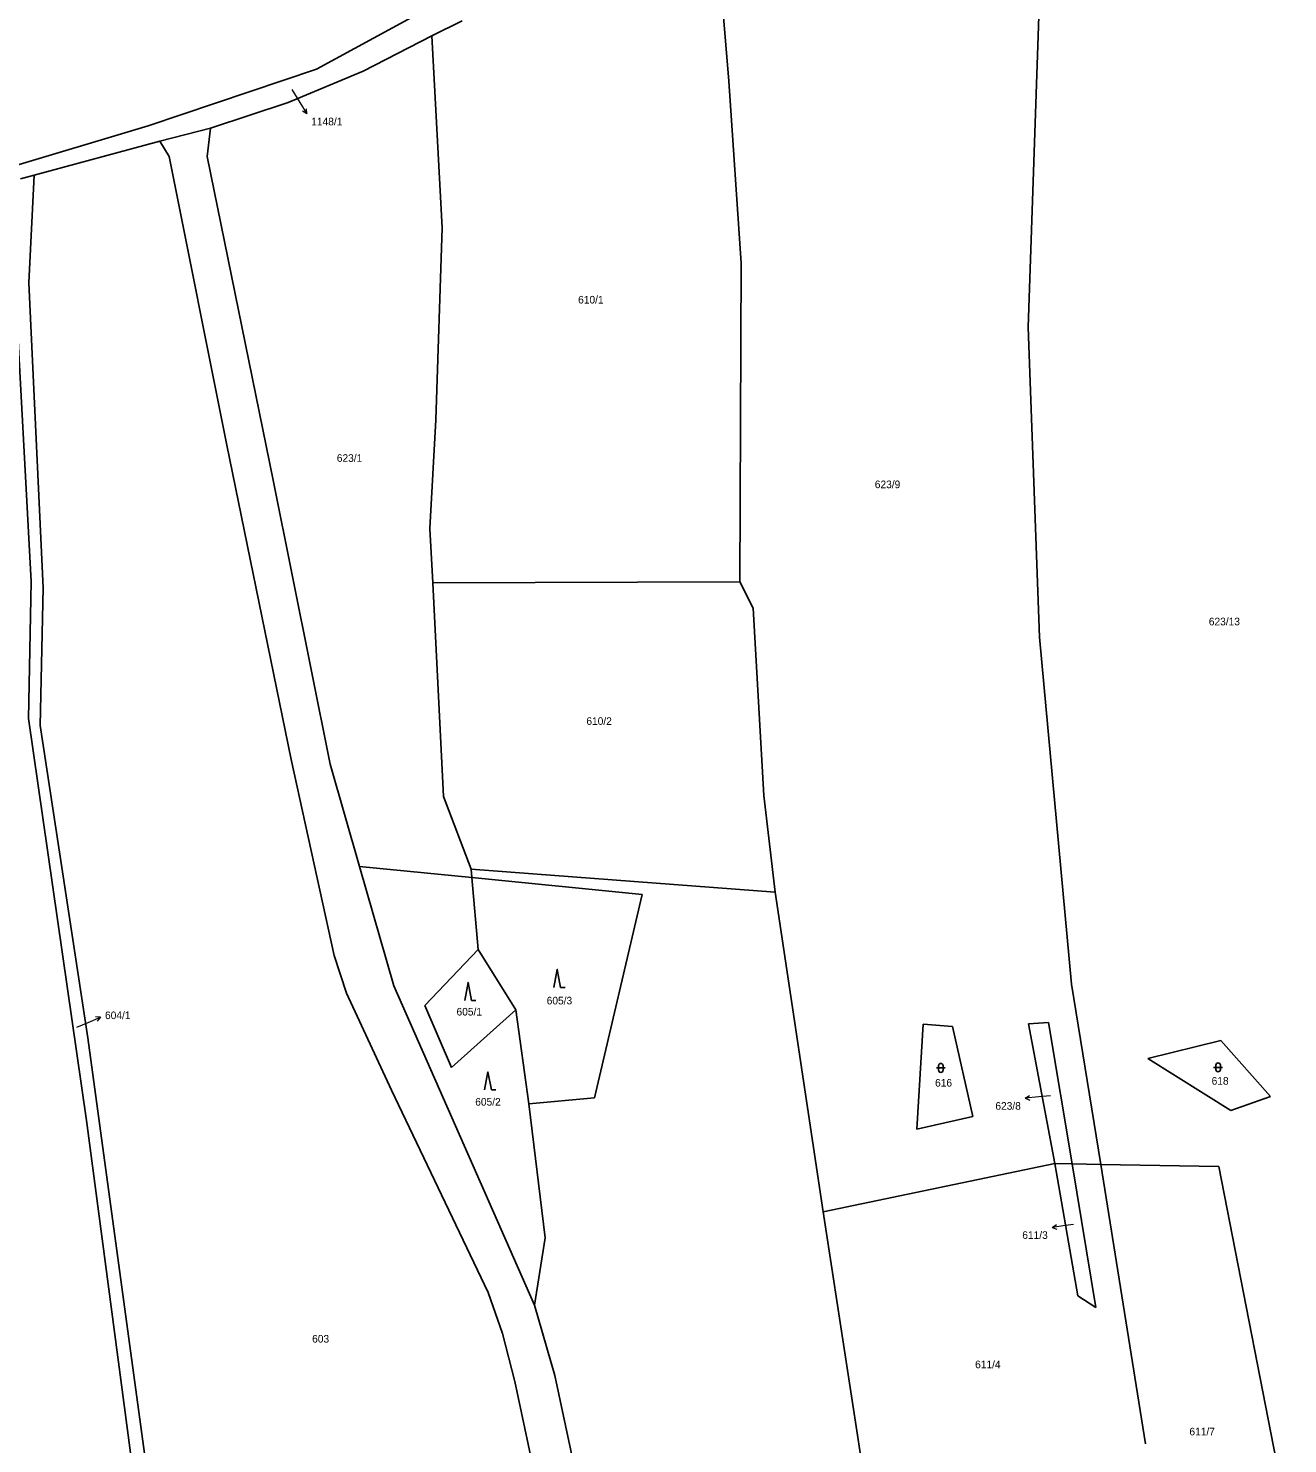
# Model space of a CAD drawing. Extents: x -765428 to -762163, y -1107632 to -1104975.
# Drawn here: x -764695.4 to -764414.2, y -1105485.1 to -1105169.2 of the extents above; entities that cross this region are included whole.
import ezdxf
from ezdxf.enums import TextEntityAlignment as Align

# ---------------------------------------------------------------- set-up
doc = ezdxf.new("R2010")
doc.units = 0
doc.header["$LTSCALE"] = 0.68
for name, color, linetype, lineweight in [('1', 7, 'Continuous', 25), ('3', 7, 'Continuous', 25), ('7', 7, 'Continuous', 13)]:
    doc.layers.add(name, color=color, linetype=linetype, lineweight=lineweight)
doc.layers.add('2', color=7, linetype='Continuous')

msp = doc.modelspace()

# ---------------------------------------------------------------- linework, layer by layer
at = {"layer": '1'}
for p, q in [((-764472.15, -1105235.89), (-764466.74, -1105081.66)), ((-764541.95, -1105146.03), (-764538.95, -1105180.96)), ((-764631.08, -1105178.3), (-764585.1, -1105153.29)), ((-764605.34, -1105170.88), (-764598.53, -1105167.48)), ((-764620.63, -1105178.73), (-764605.34, -1105170.88)), ((-764603.03, -1105213.7), (-764605.34, -1105170.88)), ((-764668.63, -1105190.94), (-764631.08, -1105178.3)), ((-764637.4, -1105185.76), (-764620.63, -1105178.73)), ((-764538.95, -1105180.96), (-764536.21, -1105221.63)), ((-764654.71, -1105191.48), (-764637.4, -1105185.76)), ((-764701.19, -1105200.73), (-764668.63, -1105190.94)), ((-764666.03, -1105194.38), (-764654.71, -1105191.48)), ((-764654.71, -1105191.48), (-764655.45, -1105197.76)), ((-764694.13, -1105201.96), (-764666.03, -1105194.38)), ((-764663.96, -1105197.76), (-764666.03, -1105194.38)), ((-764651.12, -1105262.24), (-764663.96, -1105197.76)), ((-764655.45, -1105197.76), (-764640.74, -1105270.08)), ((-764697.21, -1105202.78), (-764694.13, -1105201.96)), ((-764694.13, -1105201.96), (-764695.3, -1105225.99)), ((-764604.4, -1105256.59), (-764603.03, -1105213.7)), ((-764536.21, -1105221.63), (-764536.52, -1105292.75)), ((-764694.8, -1105292.7), (-764698.46, -1105225.08)), ((-764695.3, -1105225.99), (-764692.1, -1105294.06)), ((-764469.58, -1105305.06), (-764472.15, -1105235.89)), ((-764636.7, -1105332.4), (-764651.12, -1105262.24)), ((-764640.74, -1105270.08), (-764628.02, -1105333.47)), ((-764695.42, -1105323.28), (-764694.8, -1105292.7)), ((-764692.1, -1105294.06), (-764692.76, -1105324.83)), ((-764536.52, -1105292.75), (-764605.11, -1105292.98)), ((-764602.7, -1105340.64), (-764605.11, -1105292.98)), ((-764533.53, -1105298.64), (-764536.52, -1105292.75)), ((-764531.13, -1105340.45), (-764533.53, -1105298.64)), ((-764462.44, -1105382.57), (-764469.58, -1105305.06)), ((-764682.42, -1105413.02), (-764695.42, -1105323.28)), ((-764692.76, -1105324.83), (-764682.15, -1105394.5)), ((-764627.15, -1105376.12), (-764636.7, -1105332.4)), ((-764628.02, -1105333.47), (-764621.46, -1105356.29)), ((-764596.54, -1105356.9), (-764602.7, -1105340.64)), ((-764528.63, -1105362), (-764531.13, -1105340.45)), ((-764621.46, -1105356.29), (-764613.81, -1105382.9)), ((-764596.38, -1105358.77), (-764621.46, -1105356.29)), ((-764596.38, -1105358.77), (-764596.54, -1105356.9)), ((-764596.54, -1105356.9), (-764528.63, -1105362)), ((-764594.97, -1105374.84), (-764596.38, -1105358.77)), ((-764558.36, -1105362.53), (-764596.38, -1105358.77)), ((-764517.92, -1105433.38), (-764528.63, -1105362)), ((-764568.96, -1105407.93), (-764558.36, -1105362.53)), ((-764606.85, -1105387.31), (-764594.97, -1105374.84)), ((-764594.97, -1105374.84), (-764586.56, -1105388.29)), ((-764624.34, -1105384.55), (-764627.15, -1105376.12)), ((-764613.81, -1105382.9), (-764582.41, -1105454.21)), ((-764462.44, -1105382.57), (-764455.91, -1105422.81)), ((-764614.3, -1105406.2), (-764624.34, -1105384.55)), ((-764600.89, -1105401.18), (-764606.85, -1105387.31)), ((-764586.56, -1105388.29), (-764600.89, -1105401.18)), ((-764586.56, -1105388.29), (-764583.62, -1105409.29)), ((-764495.55, -1105391.49), (-764496.96, -1105414.96)), ((-764489.03, -1105392.03), (-764495.55, -1105391.49)), ((-764484.47, -1105412.09), (-764489.03, -1105392.03)), ((-764467.58, -1105391.08), (-764472.05, -1105391.44)), ((-764472.05, -1105391.44), (-764466.17, -1105422.62)), ((-764467.58, -1105391.08), (-764462.31, -1105422.69)), ((-764682.15, -1105394.5), (-764666.69, -1105507.59)), ((-764445.38, -1105399.13), (-764429.11, -1105395.1)), ((-764429.11, -1105395.1), (-764417.97, -1105407.63)), ((-764426.84, -1105410.79), (-764445.38, -1105399.13)), ((-764592.7, -1105451.41), (-764614.3, -1105406.2)), ((-764583.62, -1105409.29), (-764568.96, -1105407.93)), ((-764580, -1105439.16), (-764583.62, -1105409.29)), ((-764417.97, -1105407.63), (-764426.84, -1105410.79)), ((-764496.96, -1105414.96), (-764484.47, -1105412.09)), ((-764671.4, -1105496.51), (-764682.42, -1105413.02)), ((-764466.17, -1105422.62), (-764461.01, -1105452.13)), ((-764462.31, -1105422.69), (-764466.17, -1105422.62)), ((-764462.31, -1105422.69), (-764457.03, -1105454.73)), ((-764455.91, -1105422.81), (-764462.31, -1105422.69)), ((-764455.91, -1105422.81), (-764445.9, -1105485.2)), ((-764429.51, -1105423.29), (-764455.91, -1105422.81)), ((-764414.16, -1105501.89), (-764429.51, -1105423.29)), ((-764582.41, -1105454.21), (-764580, -1105439.16)), ((-764589.56, -1105460.5), (-764592.7, -1105451.41)), ((-764461.01, -1105452.13), (-764457.03, -1105454.73)), ((-764582.41, -1105454.21), (-764577.82, -1105469.9)), ((-764586.75, -1105471.28), (-764589.56, -1105460.5)), ((-764576.61, -1105518.88), (-764586.75, -1105471.28)), ((-764577.82, -1105469.9), (-764554.57, -1105579.66))]:
    msp.add_line(p, q, dxfattribs=at)
for points in [[(-764605.11, -1105292.98), (-764605.75, -1105280.82), (-764604.4, -1105256.59)], [(-764466.17, -1105422.62), (-764517.92, -1105433.38), (-764496.73, -1105570.91)]]:
    msp.add_lwpolyline(points, dxfattribs=at)
at = {"layer": '3'}
for p, q in [((-764576.56, -1105383.28), (-764575.564, -1105383.28)), ((-764596.46, -1105386.18), (-764595.464, -1105386.18)), ((-764492.631, -1105401.241), (-764490.629, -1105401.241)), ((-764492.131, -1105400.741), (-764492.131, -1105401.742)), ((-764491.129, -1105401.742), (-764491.129, -1105400.741)), ((-764430.701, -1105401.121), (-764428.699, -1105401.121)), ((-764430.201, -1105400.621), (-764430.201, -1105401.622)), ((-764429.199, -1105401.622), (-764429.199, -1105400.621)), ((-764592.02, -1105406.16), (-764591.024, -1105406.16))]:
    msp.add_line(p, q, dxfattribs=at)
for points in [[(-764576.56, -1105383.28), (-764577.31, -1105379.28), (-764578.06, -1105383.28)], [(-764596.46, -1105386.18), (-764597.21, -1105382.18), (-764597.96, -1105386.18)], [(-764592.02, -1105406.16), (-764592.77, -1105402.16), (-764593.52, -1105406.16)]]:
    msp.add_lwpolyline(points, dxfattribs=at)
for centre, start, end in [((-764429.7, -1105400.6209), 0, 180), ((-764491.63, -1105400.7409), 0, 180), ((-764491.63, -1105401.7409), 180, 359.98789), ((-764429.7, -1105401.6209), 180, 359.98789)]:
    msp.add_arc(centre, 0.5, start, end, dxfattribs=at)
at = {"layer": '7'}
for p, q in [((-764633.22, -1105188.265), (-764633.326, -1105187.15)), ((-764679.298, -1105389.927), (-764680.415, -1105389.858)), ((-764472.765, -1105408.034), (-764471.716, -1105408.427)), ((-764466.752, -1105436.868), (-764465.69, -1105437.224))]:
    msp.add_line(p, q, dxfattribs=at)
for points in [[(-764636.58, -1105182.85), (-764634.81, -1105185.72), (-764633.22, -1105188.265), (-764634.175, -1105187.681)], [(-764684.56, -1105392.15), (-764682.06, -1105391.1), (-764679.298, -1105389.927), (-764680.024, -1105390.78)], [(-764467.11, -1105407.45), (-764469.78, -1105407.72), (-764472.765, -1105408.034), (-764471.821, -1105407.431)], [(-764461.99, -1105436.21), (-764463.78, -1105436.45), (-764466.752, -1105436.868), (-764465.83, -1105436.232)]]:
    msp.add_lwpolyline(points, dxfattribs=at)

# ---------------------------------------------------------------- texts
at = {"layer": '2'}
for s, p in [('1148/1', (-764632.24, -1105190.845)), ('604/1', (-764678.3, -1105390.355)), ('618', (-764431.15, -1105404.995)), ('616', (-764492.92, -1105405.425)), ('603', (-764632.04, -1105462.565))]:
    msp.add_text(s, height=1.7, dxfattribs=at).set_placement(p)
for s, p in [('610/1', (-764569.79, -1105230.615)), ('623/1', (-764623.68, -1105265.955)), ('623/9', (-764503.53, -1105271.835)), ('623/13', (-764428.3, -1105302.455)), ('610/2', (-764567.95, -1105324.675)), ('605/3', (-764576.81, -1105387.075)), ('605/1', (-764596.95, -1105389.555)), ('605/2', (-764592.77, -1105409.665)), ('611/4', (-764481.13, -1105468.295)), ('611/7', (-764433.27, -1105483.275))]:
    msp.add_text(s, height=1.7, dxfattribs=at).set_placement(p, align=Align.CENTER)
for s, p in [('623/8', (-764473.76, -1105410.585)), ('611/3', (-764467.75, -1105439.415))]:
    msp.add_text(s, height=1.7, dxfattribs=at).set_placement(p, align=Align.RIGHT)

doc.saveas('drawing.dxf')
